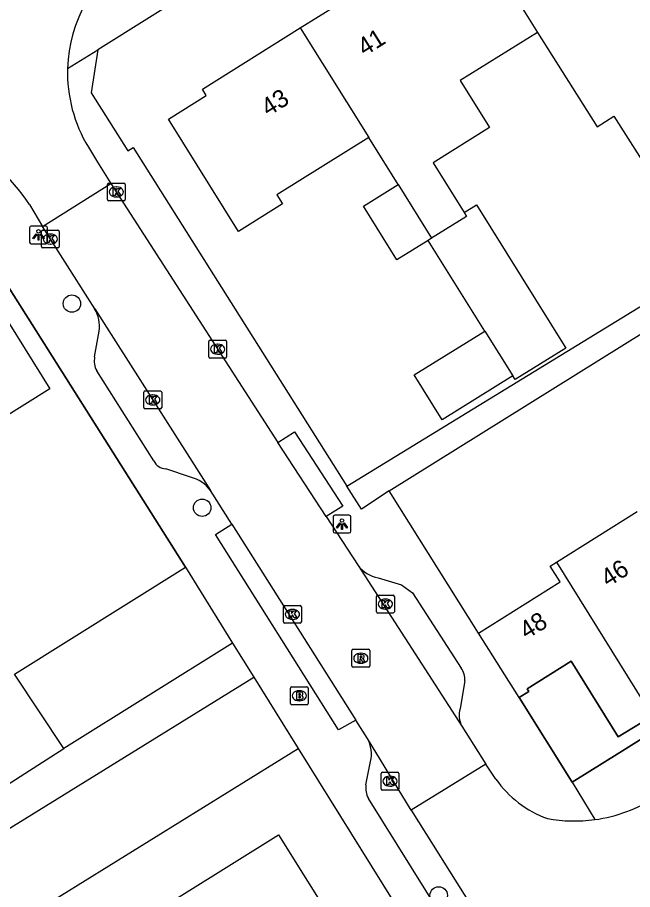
# Model space of a CAD drawing. Extents: x 159353 to 160616, y 385893 to 387321.
# Drawn here: x 159730.58 to 159765.06, y 386027.3 to 386076.22 of the extents above; entities that cross this region are included whole.
import ezdxf

# ---------------------------------------------------------------- set-up
doc = ezdxf.new("R2010")
doc.units = 0
for name, color, linetype in [('IMGEO_Boom', 7, 'Continuous'), ('IMGEO_Brandkraan', 7, 'Continuous'), ('IMGEO_Kolk', 7, 'Continuous'), ('IMGEO_Lichtpunt', 7, 'Continuous'), ('IMGEO_Muur', 7, 'Continuous'), ('IMGEO_Pand', 7, 'Continuous'), ('IMGEO_Pand_nummerreeks', 7, 'Continuous'), ('IMGEO_Pand_overbouw', 7, 'Continuous'), ('IMGEO_Rijbaan_lokaal_open', 7, 'Continuous'), ('IMGEO_Rioolput', 7, 'Continuous'), ('IMGEO_Voetpad_open', 7, 'Continuous')]:
    doc.layers.add(name, color=color, linetype=linetype)

msp = doc.modelspace()

# ---------------------------------------------------------------- linework, layer by layer
at = {"layer": 'IMGEO_Boom'}
for centre in [(159733.63, 386060.166), (159740.935, 386048.717), (159754.195, 386026.974)]:
    msp.add_circle(centre, 0.489, dxfattribs=at)
at = {"layer": 'IMGEO_Brandkraan'}
for p, q in [((159745.879, 386037.743), (159745.879, 386038.595)), ((159745.954, 386038.669), (159746.806, 386038.669)), ((159746.367, 386038.449), (159746.392, 386038.449)), ((159746.88, 386038.595), (159746.88, 386037.743)), ((159746.39, 386037.889), (159746.365, 386037.889)), ((159746.806, 386037.669), (159745.954, 386037.669))]:
    msp.add_line(p, q, dxfattribs=at)
for points in [[(159745.879, 386037.743), (159745.879, 386038.595)], [(159745.954, 386038.669), (159746.806, 386038.669)], [(159746.227, 386038.369), (159746.227, 386037.969), (159746.44, 386037.969)], [(159746.458, 386038.369), (159746.227, 386038.369)], [(159746.406, 386038.288), (159746.352, 386038.288), (159746.352, 386038.212)], [(159746.88, 386038.595), (159746.88, 386037.743)], [(159746.352, 386038.212), (159746.405, 386038.212)], [(159746.414, 386038.136), (159746.352, 386038.136), (159746.352, 386038.055)], [(159746.352, 386038.055), (159746.414, 386038.055)], [(159746.806, 386037.669), (159745.954, 386037.669)]]:
    msp.add_lwpolyline(points, dxfattribs=at)
for centre, radius, start, end in [((159745.956, 386038.593), 0.0765, 91.552, 178.448), ((159745.956, 386038.593), 0.0765, 91.552, 178.448), ((159746.407, 386038.25), 0.0379, 267.8285, 90.9355), ((159746.462, 386038.224), 0.145, 59.4692, 91.5367), ((159746.487, 386038.271), 0.0922, 285.5137, 58.1501), ((159746.804, 386038.593), 0.0765, 1.552, 88.448), ((159746.804, 386038.593), 0.0765, 1.552, 88.448), ((159745.956, 386037.745), 0.0765, 181.552, 268.448), ((159745.956, 386037.745), 0.0765, 181.552, 268.448), ((159746.415, 386038.095), 0.0404, 269.8759, 90.5077), ((159746.446, 386038.22), 0.251, 268.6676, 293.5347), ((159746.492, 386038.079), 0.105, 301.3115, 78.989), ((159746.804, 386037.745), 0.0765, 271.552, 358.448), ((159746.804, 386037.745), 0.0765, 271.552, 358.448)]:
    msp.add_arc(centre, radius, start, end, dxfattribs=at)
for centre, major_axis, ratio, start_param, end_param in [((159746.366, 386038.169), (-0.387, 0.002), 0.722429, 4.712389, 7.853982), ((159746.391, 386038.169), (-0.39, 0.002), 0.717154, 1.570796, 4.712389)]:
    msp.add_ellipse(centre, major_axis=major_axis, ratio=ratio, start_param=start_param, end_param=end_param, dxfattribs=at)
at = {"layer": 'IMGEO_Kolk'}
for p, q in [((159735.622, 386066.003), (159735.622, 386066.855)), ((159735.697, 386066.929), (159736.549, 386066.929)), ((159736.11, 386066.709), (159736.135, 386066.709)), ((159736.623, 386066.855), (159736.623, 386066.003)), ((159736.133, 386066.149), (159736.108, 386066.149)), ((159736.549, 386065.929), (159735.697, 386065.929)), ((159731.919, 386063.363), (159731.919, 386064.215)), ((159731.994, 386064.289), (159732.846, 386064.289)), ((159732.92, 386064.215), (159732.92, 386063.363)), ((159732.407, 386064.069), (159732.432, 386064.069)), ((159732.846, 386063.289), (159731.994, 386063.289)), ((159732.43, 386063.509), (159732.405, 386063.509)), ((159741.303, 386057.184), (159741.303, 386058.036)), ((159741.378, 386058.11), (159742.23, 386058.11)), ((159741.791, 386057.89), (159741.816, 386057.89)), ((159742.304, 386058.036), (159742.304, 386057.184)), ((159741.814, 386057.33), (159741.789, 386057.33)), ((159742.23, 386057.11), (159741.378, 386057.11)), ((159737.663, 386054.34), (159737.663, 386055.192)), ((159737.738, 386055.266), (159738.59, 386055.266)), ((159738.151, 386055.046), (159738.176, 386055.046)), ((159738.664, 386055.192), (159738.664, 386054.34)), ((159738.174, 386054.486), (159738.149, 386054.486)), ((159738.59, 386054.266), (159737.738, 386054.266)), ((159750.706, 386042.885), (159750.706, 386043.737)), ((159750.781, 386043.811), (159751.633, 386043.811)), ((159751.707, 386043.737), (159751.707, 386042.885)), ((159745.493, 386042.311), (159745.493, 386043.163)), ((159745.568, 386043.237), (159746.42, 386043.237)), ((159746.494, 386043.163), (159746.494, 386042.311)), ((159751.194, 386043.591), (159751.219, 386043.591)), ((159745.981, 386043.017), (159746.006, 386043.017)), ((159751.633, 386042.811), (159750.781, 386042.811)), ((159751.217, 386043.031), (159751.192, 386043.031)), ((159746.42, 386042.237), (159745.568, 386042.237)), ((159746.004, 386042.457), (159745.979, 386042.457)), ((159751.037, 386033.879), (159751.889, 386033.879)), ((159750.962, 386032.953), (159750.962, 386033.805)), ((159751.45, 386033.659), (159751.475, 386033.659)), ((159751.963, 386033.805), (159751.963, 386032.953)), ((159751.889, 386032.879), (159751.037, 386032.879)), ((159751.473, 386033.099), (159751.448, 386033.099))]:
    msp.add_line(p, q, dxfattribs=at)
for points in [[(159735.622, 386066.003), (159735.622, 386066.855)], [(159735.697, 386066.929), (159736.549, 386066.929)], [(159735.943, 386066.629), (159736.066, 386066.629), (159736.066, 386066.478), (159736.196, 386066.629), (159736.36, 386066.629), (159736.214, 386066.478), (159736.367, 386066.229), (159736.215, 386066.229), (159736.13, 386066.393), (159736.066, 386066.326), (159736.066, 386066.229), (159735.943, 386066.229), (159735.943, 386066.629)], [(159736.623, 386066.855), (159736.623, 386066.003)], [(159736.549, 386065.929), (159735.697, 386065.929)], [(159731.919, 386063.363), (159731.919, 386064.215)], [(159731.994, 386064.289), (159732.846, 386064.289)], [(159732.92, 386064.215), (159732.92, 386063.363)], [(159732.24, 386063.989), (159732.363, 386063.989), (159732.363, 386063.838), (159732.493, 386063.989), (159732.657, 386063.989), (159732.511, 386063.838), (159732.664, 386063.589), (159732.512, 386063.589), (159732.427, 386063.753), (159732.363, 386063.686), (159732.363, 386063.589), (159732.24, 386063.589), (159732.24, 386063.989)], [(159732.846, 386063.289), (159731.994, 386063.289)], [(159741.303, 386057.184), (159741.303, 386058.036)], [(159741.378, 386058.11), (159742.23, 386058.11)], [(159741.624, 386057.81), (159741.747, 386057.81), (159741.747, 386057.659), (159741.877, 386057.81), (159742.041, 386057.81), (159741.895, 386057.659), (159742.048, 386057.41), (159741.896, 386057.41), (159741.811, 386057.574), (159741.747, 386057.507), (159741.747, 386057.41), (159741.624, 386057.41), (159741.624, 386057.81)], [(159742.304, 386058.036), (159742.304, 386057.184)], [(159742.23, 386057.11), (159741.378, 386057.11)], [(159737.663, 386054.34), (159737.663, 386055.192)], [(159737.738, 386055.266), (159738.59, 386055.266)], [(159737.984, 386054.966), (159738.107, 386054.966), (159738.107, 386054.815), (159738.237, 386054.966), (159738.401, 386054.966), (159738.255, 386054.815), (159738.408, 386054.566), (159738.256, 386054.566), (159738.171, 386054.73), (159738.107, 386054.663), (159738.107, 386054.566), (159737.984, 386054.566), (159737.984, 386054.966)], [(159738.664, 386055.192), (159738.664, 386054.34)], [(159738.59, 386054.266), (159737.738, 386054.266)], [(159750.706, 386042.885), (159750.706, 386043.737)], [(159750.781, 386043.811), (159751.633, 386043.811)], [(159751.707, 386043.737), (159751.707, 386042.885)], [(159745.493, 386042.311), (159745.493, 386043.163)], [(159745.568, 386043.237), (159746.42, 386043.237)], [(159746.494, 386043.163), (159746.494, 386042.311)], [(159751.027, 386043.511), (159751.15, 386043.511), (159751.15, 386043.36), (159751.28, 386043.511), (159751.444, 386043.511), (159751.298, 386043.36), (159751.451, 386043.111), (159751.299, 386043.111), (159751.214, 386043.275), (159751.15, 386043.208), (159751.15, 386043.111), (159751.027, 386043.111), (159751.027, 386043.511)], [(159745.814, 386042.937), (159745.937, 386042.937), (159745.937, 386042.786), (159746.067, 386042.937), (159746.231, 386042.937), (159746.085, 386042.786), (159746.238, 386042.537), (159746.086, 386042.537), (159746.001, 386042.701), (159745.937, 386042.634), (159745.937, 386042.537), (159745.814, 386042.537), (159745.814, 386042.937)], [(159751.633, 386042.811), (159750.781, 386042.811)], [(159746.42, 386042.237), (159745.568, 386042.237)], [(159751.037, 386033.879), (159751.889, 386033.879)], [(159750.962, 386032.953), (159750.962, 386033.805)], [(159751.283, 386033.579), (159751.406, 386033.579), (159751.406, 386033.428), (159751.536, 386033.579), (159751.7, 386033.579), (159751.554, 386033.428), (159751.707, 386033.179), (159751.555, 386033.179), (159751.47, 386033.343), (159751.406, 386033.276), (159751.406, 386033.179), (159751.283, 386033.179), (159751.283, 386033.579)], [(159751.963, 386033.805), (159751.963, 386032.953)], [(159751.889, 386032.879), (159751.037, 386032.879)]]:
    msp.add_lwpolyline(points, dxfattribs=at)
for centre, start, end in [((159735.699, 386066.853), 91.552, 178.448), ((159735.699, 386066.853), 91.552, 178.448), ((159736.547, 386066.853), 1.552, 88.448), ((159736.547, 386066.853), 1.552, 88.448), ((159735.699, 386066.005), 181.552, 268.448), ((159735.699, 386066.005), 181.552, 268.448), ((159736.547, 386066.005), 271.552, 358.448), ((159736.547, 386066.005), 271.552, 358.448), ((159731.996, 386064.213), 91.552, 178.448), ((159731.996, 386064.213), 91.552, 178.448), ((159732.844, 386064.213), 1.552, 88.448), ((159732.844, 386064.213), 1.552, 88.448), ((159731.996, 386063.365), 181.552, 268.448), ((159731.996, 386063.365), 181.552, 268.448), ((159732.844, 386063.365), 271.552, 358.448), ((159732.844, 386063.365), 271.552, 358.448), ((159741.38, 386058.034), 91.552, 178.448), ((159741.38, 386058.034), 91.552, 178.448), ((159742.228, 386058.034), 1.552, 88.448), ((159742.228, 386058.034), 1.552, 88.448), ((159741.38, 386057.186), 181.552, 268.448), ((159741.38, 386057.186), 181.552, 268.448), ((159742.228, 386057.186), 271.552, 358.448), ((159742.228, 386057.186), 271.552, 358.448), ((159737.74, 386055.19), 91.552, 178.448), ((159737.74, 386055.19), 91.552, 178.448), ((159738.588, 386055.19), 1.552, 88.448), ((159738.588, 386055.19), 1.552, 88.448), ((159737.74, 386054.342), 181.552, 268.448), ((159737.74, 386054.342), 181.552, 268.448), ((159738.588, 386054.342), 271.552, 358.448), ((159738.588, 386054.342), 271.552, 358.448), ((159750.783, 386043.735), 91.552, 178.448), ((159750.783, 386043.735), 91.552, 178.448), ((159751.631, 386043.735), 1.552, 88.448), ((159751.631, 386043.735), 1.552, 88.448), ((159745.57, 386043.161), 91.552, 178.448), ((159745.57, 386043.161), 91.552, 178.448), ((159746.418, 386043.161), 1.552, 88.448), ((159746.418, 386043.161), 1.552, 88.448), ((159750.783, 386042.887), 181.552, 268.448), ((159750.783, 386042.887), 181.552, 268.448), ((159751.631, 386042.887), 271.552, 358.448), ((159751.631, 386042.887), 271.552, 358.448), ((159745.57, 386042.313), 181.552, 268.448), ((159745.57, 386042.313), 181.552, 268.448), ((159746.418, 386042.313), 271.552, 358.448), ((159746.418, 386042.313), 271.552, 358.448), ((159751.039, 386033.803), 91.552, 178.448), ((159751.039, 386033.803), 91.552, 178.448), ((159751.887, 386033.803), 1.552, 88.448), ((159751.887, 386033.803), 1.552, 88.448), ((159751.039, 386032.955), 181.552, 268.448), ((159751.039, 386032.955), 181.552, 268.448), ((159751.887, 386032.955), 271.552, 358.448), ((159751.887, 386032.955), 271.552, 358.448)]:
    msp.add_arc(centre, 0.0765, start, end, dxfattribs=at)
for centre, major_axis, ratio, start_param, end_param in [((159736.109, 386066.429), (-0.387, 0.002), 0.722429, 4.712389, 7.853982), ((159736.134, 386066.429), (-0.39, 0.002), 0.717154, 1.570796, 4.712389), ((159732.406, 386063.789), (-0.387, 0.002), 0.722429, 4.712389, 7.853982), ((159732.431, 386063.789), (-0.39, 0.002), 0.717154, 1.570796, 4.712389), ((159741.79, 386057.61), (-0.387, 0.002), 0.722429, 4.712389, 7.853982), ((159741.815, 386057.61), (-0.39, 0.002), 0.717154, 1.570796, 4.712389), ((159738.15, 386054.766), (-0.387, 0.002), 0.722429, 4.712389, 7.853982), ((159738.175, 386054.766), (-0.39, 0.002), 0.717154, 1.570796, 4.712389), ((159751.193, 386043.311), (-0.387, 0.002), 0.722429, 4.712389, 7.853982), ((159751.218, 386043.311), (-0.39, 0.002), 0.717154, 1.570796, 4.712389), ((159745.98, 386042.737), (-0.387, 0.002), 0.722429, 4.712389, 7.853982), ((159746.005, 386042.737), (-0.39, 0.002), 0.717154, 1.570796, 4.712389), ((159751.449, 386033.379), (-0.387, 0.002), 0.722429, 4.712389, 7.853982), ((159751.474, 386033.379), (-0.39, 0.002), 0.717154, 1.570796, 4.712389)]:
    msp.add_ellipse(centre, major_axis=major_axis, ratio=ratio, start_param=start_param, end_param=end_param, dxfattribs=at)
at = {"layer": 'IMGEO_Lichtpunt'}
for p, q in [((159731.262, 386064.423), (159731.262, 386063.616)), ((159731.262, 386064.423), (159731.262, 386063.616)), ((159732.164, 386064.518), (159731.356, 386064.518)), ((159732.164, 386064.518), (159731.356, 386064.518)), ((159732.258, 386063.616), (159732.258, 386064.423)), ((159732.258, 386063.616), (159732.258, 386064.423)), ((159731.356, 386063.522), (159732.164, 386063.522)), ((159731.356, 386063.522), (159732.164, 386063.522)), ((159748.273, 386048.204), (159748.273, 386047.397)), ((159748.273, 386048.204), (159748.273, 386047.397)), ((159749.175, 386048.299), (159748.367, 386048.299)), ((159749.175, 386048.299), (159748.367, 386048.299)), ((159749.269, 386047.397), (159749.269, 386048.204)), ((159749.269, 386047.397), (159749.269, 386048.204)), ((159748.367, 386047.303), (159749.175, 386047.303)), ((159748.367, 386047.303), (159749.175, 386047.303))]:
    msp.add_line(p, q, dxfattribs=at)
for points in [[(159731.636, 386064.087), (159731.675, 386064.059), (159731.487, 386063.797), (159731.449, 386063.824), (159731.636, 386064.087)], [(159731.738, 386064.039), (159731.785, 386064.039), (159731.785, 386063.717), (159731.738, 386063.717), (159731.738, 386064.039)], [(159731.848, 386064.059), (159731.886, 386064.086), (159732.073, 386063.824), (159732.034, 386063.796), (159731.848, 386064.059)], [(159748.647, 386047.868), (159748.686, 386047.84), (159748.498, 386047.578), (159748.46, 386047.605), (159748.647, 386047.868)], [(159748.749, 386047.82), (159748.796, 386047.82), (159748.796, 386047.498), (159748.749, 386047.498), (159748.749, 386047.82)], [(159748.859, 386047.84), (159748.897, 386047.867), (159749.084, 386047.605), (159749.045, 386047.577), (159748.859, 386047.84)]]:
    msp.add_lwpolyline(points, dxfattribs=at)
for centre in [(159731.761, 386064.221), (159748.772, 386048.002)]:
    msp.add_circle(centre, 0.0994, dxfattribs=at)
for centre, start, end in [((159731.356, 386064.423), 90, 180), ((159731.356, 386064.423), 90, 180), ((159732.164, 386064.423), 0, 90), ((159732.164, 386064.423), 0, 90), ((159731.356, 386063.616), 180, 270), ((159731.356, 386063.616), 180, 270), ((159732.164, 386063.616), 270, 0), ((159732.164, 386063.616), 270, 360), ((159748.367, 386048.204), 90, 180), ((159748.367, 386048.204), 90, 180), ((159749.175, 386048.204), 0, 90), ((159749.175, 386048.204), 0, 90), ((159748.367, 386047.397), 180, 270), ((159748.367, 386047.397), 180, 270), ((159749.175, 386047.397), 270, 0), ((159749.175, 386047.397), 270, 360)]:
    msp.add_arc(centre, 0.0946, start, end, dxfattribs=at)
at = {"layer": 'IMGEO_Muur'}
for points in [[(159739.998, 386045.377), (159726.053, 386067.427)], [(159756.434, 386041.685), (159751.412, 386049.66)]]:
    msp.add_lwpolyline(points, dxfattribs=at)
at = {"layer": 'IMGEO_Pand'}
for points in [[(159746.435, 386075.635), (159751.559, 386078.84), (159752.882, 386076.718), (159757.19, 386079.405)], [(159757.19, 386079.405), (159758.698, 386077.014), (159759.732, 386075.374)], [(159759.732, 386075.374), (159763.073, 386070.078), (159764.019, 386070.675), (159765.576, 386068.207), (159774.279, 386073.697), (159772.722, 386076.165), (159772.322, 386076.799)], [(159750.274, 386069.478), (159745.119, 386066.265), (159745.436, 386065.756), (159742.966, 386064.216), (159739.04, 386070.512), (159741.167, 386071.842), (159740.943, 386072.2), (159746.435, 386075.635)], [(159746.435, 386075.635), (159750.274, 386069.478)], [(159759.732, 386075.374), (159755.402, 386072.674), (159757.046, 386070.036), (159753.88, 386068.063), (159755.614, 386065.282)], [(159751.919, 386066.841), (159750.274, 386069.478)], [(159753.599, 386063.715), (159751.849, 386062.625), (159749.976, 386065.63), (159751.919, 386066.841)], [(159751.919, 386066.841), (159753.793, 386063.836)], [(159755.614, 386065.282), (159756.304, 386065.712), (159761.317, 386057.675), (159758.472, 386055.901), (159758.341, 386056.112)], [(159755.614, 386065.282), (159755.753, 386065.058), (159753.793, 386063.836)], [(159753.793, 386063.836), (159753.599, 386063.715)], [(159756.774, 386058.623), (159753.599, 386063.715)], [(159718.85, 386058.374), (159724.039, 386061.618), (159725.451, 386059.359), (159728.653, 386061.361), (159732.387, 386055.393), (159729.564, 386053.627), (159728.326, 386055.605), (159722.758, 386052.122)], [(159758.341, 386056.112), (159754.393, 386053.65), (159752.827, 386056.162), (159756.774, 386058.623)], [(159756.774, 386058.623), (159758.341, 386056.112)], [(159760.791, 386045.66), (159765.322, 386048.505)], [(159756.434, 386041.685), (159761.007, 386044.556), (159760.449, 386045.445), (159760.791, 386045.66)], [(159760.791, 386045.66), (159766.564, 386036.364)], [(159733.186, 386035.211), (159730.405, 386039.383), (159739.998, 386045.377)], [(159739.998, 386045.377), (159742.641, 386041.129)], [(159758.7, 386038.075), (159756.434, 386041.685)], [(159742.641, 386041.129), (159733.186, 386035.211)], [(159758.7, 386038.075), (159759.248, 386038.413), (159759.159, 386038.558), (159761.62, 386040.107), (159764.257, 386035.863), (159765.538, 386036.658), (159765.962, 386035.991)], [(159740.019, 386019.428), (159739.9, 386019.62), (159740.475, 386019.981), (159737.155, 386025.338), (159745.219, 386030.364), (159748.551, 386025.02), (159749.137, 386025.384), (159749.263, 386025.183)]]:
    msp.add_lwpolyline(points, dxfattribs=at)
at = {"layer": 'IMGEO_Pand_overbouw'}
msp.add_lwpolyline([(159758.7, 386038.075), (159761.674, 386033.329), (159764.352, 386034.991), (159765.962, 386035.991), (159765.538, 386036.658), (159764.257, 386035.863), (159761.62, 386040.107), (159759.159, 386038.558), (159759.248, 386038.413)], close=True, dxfattribs=at)
at = {"layer": 'IMGEO_Rijbaan_lokaal_open'}
for points in [[(159734.553, 386068.939), (159735.069, 386068.094), (159735.815, 386066.908)], [(159731.979, 386064.484), (159735.815, 386066.908)], [(159735.815, 386066.908), (159745.179, 386052.371)], [(159731.248, 386065.731), (159731.979, 386064.484)], [(159734.907, 386059.872), (159731.979, 386064.484)], [(159734.907, 386059.872), (159741.407, 386049.679)], [(159747.883, 386048.224), (159745.179, 386052.371)], [(159742.601, 386047.804), (159741.407, 386049.679)], [(159747.883, 386048.224), (159749.673, 386045.484)], [(159742.601, 386047.804), (159749.546, 386036.81)], [(159749.673, 386045.484), (159755.487, 386036.469)], [(159711.277, 386019.075), (159743.822, 386039.222)], [(159743.822, 386039.222), (159746.307, 386035.207)], [(159750.194, 386035.775), (159749.546, 386036.81)], [(159755.487, 386036.469), (159756.838, 386034.337)], [(159752.658, 386031.759), (159750.194, 386035.775)], [(159728.436, 386024.138), (159729.047, 386024.522), (159746.307, 386035.207)], [(159756.838, 386034.337), (159752.658, 386031.759)], [(159757.402, 386033.5), (159756.838, 386034.337)], [(159752.658, 386031.759), (159762.791, 386015.603)]]:
    msp.add_lwpolyline(points, dxfattribs=at)
for centre, radius, start, end in [((159741.429, 386073.115), 8.044, 122.3186, 178.2895), ((159741.442, 386073.118), 8.057, 178.3151, 211.2423), ((159721.478, 386059.203), 11.751, 33.7497, 60.6789), ((159762.267, 386036.85), 5.907, 214.5533, 250.4477), ((159761.802, 386039.568), 8.423, 277.8085, 303.0153), ((159761.809, 386039.56), 8.414, 259.6008, 277.7679)]:
    msp.add_arc(centre, radius, start, end, dxfattribs=at)
at = {"layer": 'IMGEO_Rioolput'}
for p, q in [((159749.327, 386039.851), (159749.327, 386040.703)), ((159749.402, 386040.777), (159750.254, 386040.777)), ((159750.328, 386040.703), (159750.328, 386039.851)), ((159749.815, 386040.557), (159749.84, 386040.557)), ((159750.254, 386039.777), (159749.402, 386039.777)), ((159749.838, 386039.997), (159749.813, 386039.997))]:
    msp.add_line(p, q, dxfattribs=at)
for points in [[(159749.327, 386039.851), (159749.327, 386040.703)], [(159749.402, 386040.777), (159750.254, 386040.777)], [(159750.328, 386040.703), (159750.328, 386039.851)], [(159749.916, 386040.475), (159749.664, 386040.477), (159749.664, 386040.077)], [(159749.664, 386040.077), (159749.788, 386040.077), (159749.788, 386040.239), (159749.799, 386040.239)], [(159749.842, 386040.396), (159749.788, 386040.396), (159749.788, 386040.315)], [(159749.788, 386040.315), (159749.84, 386040.315)], [(159749.846, 386040.21), (159749.917, 386040.077), (159750.057, 386040.077), (159749.992, 386040.203)], [(159750.254, 386039.777), (159749.402, 386039.777)]]:
    msp.add_lwpolyline(points, dxfattribs=at)
for centre, radius, start, end in [((159749.404, 386040.701), 0.0765, 91.552, 178.448), ((159749.404, 386040.701), 0.0765, 91.552, 178.448), ((159750.252, 386040.701), 0.0765, 1.552, 88.448), ((159750.252, 386040.701), 0.0765, 1.552, 88.448), ((159749.798, 386040.186), 0.0533, 26.0293, 88.6989), ((159749.824, 386040.504), 0.19, 274.7715, 282.9687), ((159749.848, 386040.3), 0.0964, 77.0061, 93.1865), ((159749.862, 386040.357), 0.0378, 276.6634, 79.6772), ((159749.915, 386040.365), 0.109, 350.3612, 89.416), ((159749.913, 386040.365), 0.112, 277.5842, 350.9817), ((159749.897, 386040.15), 0.108, 29.5134, 73.7905), ((159749.404, 386039.853), 0.0765, 181.552, 268.448), ((159749.404, 386039.853), 0.0765, 181.552, 268.448), ((159750.252, 386039.853), 0.0765, 271.552, 358.448), ((159750.252, 386039.853), 0.0765, 271.552, 358.448)]:
    msp.add_arc(centre, radius, start, end, dxfattribs=at)
for centre, major_axis, ratio, start_param, end_param in [((159749.814, 386040.277), (-0.387, 0.002), 0.722429, 4.712389, 7.853982), ((159749.839, 386040.277), (-0.39, 0.002), 0.717154, 1.570796, 4.712389)]:
    msp.add_ellipse(centre, major_axis=major_axis, ratio=ratio, start_param=start_param, end_param=end_param, dxfattribs=at)
at = {"layer": 'IMGEO_Voetpad_open'}
for points in [[(159846.595, 386144.231), (159735.083, 386074.392)], [(159751.412, 386049.66), (159862.072, 386118.665)], [(159749.045, 386049.918), (159785.705, 386072.384), (159811.147, 386088.283)], [(159733.388, 386073.355), (159735.083, 386074.392)], [(159735.083, 386074.392), (159734.716, 386071.987), (159736.771, 386068.736), (159737.062, 386068.923), (159749.045, 386049.918)], [(159724.652, 386067.823), (159726.053, 386067.427), (159739.998, 386045.377)], [(159734.906, 386057.179), (159735.16, 386058.627)], [(159738.227, 386051.347), (159735.021, 386056.397)], [(159745.179, 386052.371), (159746.105, 386052.968), (159748.811, 386048.809), (159747.883, 386048.224)], [(159740.28, 386050.429), (159738.891, 386050.907)], [(159751.412, 386049.66), (159749.859, 386048.628), (159749.045, 386049.918)], [(159756.434, 386041.685), (159751.412, 386049.66)], [(159749.546, 386036.81), (159748.568, 386036.254), (159741.681, 386047.216), (159742.601, 386047.804)], [(159750.795, 386044.778), (159752.115, 386044.4), (159752.734, 386043.944), (159755.456, 386039.725)], [(159742.641, 386041.129), (159743.822, 386039.222)], [(159755.666, 386039.015), (159755.391, 386037.448)], [(159761.674, 386033.329), (159758.7, 386038.075)], [(159765.962, 386035.991), (159764.352, 386034.991), (159761.674, 386033.329)], [(159712.435, 386021.927), (159733.186, 386035.211)], [(159746.307, 386035.207), (159771.719, 385994.399)], [(159750.109, 386033.166), (159750.371, 386034.478)], [(159761.674, 386033.329), (159762.946, 386031.223)], [(159773.04, 385995.833), (159750.25, 386032.416)]]:
    msp.add_lwpolyline(points, dxfattribs=at)
for centre, radius, start, end in [((159733.215, 386058.88), 1.961, 352.5906, 30.383), ((159736.045, 386056.947), 1.163, 168.4951, 208.2367), ((159738.912, 386051.659), 0.753, 204.5261, 268.413), ((159739.786, 386048.465), 2.025, 36.8274, 75.8863), ((159751.155, 386046.595), 1.852, 216.8548, 258.7862), ((159754.441, 386039.039), 1.225, 358.8862, 34.0675), ((159756.711, 386037.083), 1.369, 164.5472, 206.6538), ((159748.641, 386034.902), 1.781, 346.2146, 29.3275), ((159751.443, 386033.029), 1.342, 174.1225, 207.1721)]:
    msp.add_arc(centre, radius, start, end, dxfattribs=at)

# ---------------------------------------------------------------- texts
at = {"layer": 'IMGEO_Pand_nummerreeks'}
for s, rotation, p in [('41', 32.0226, (159750.04, 386074.021)), ('43', 32.0248, (159744.636, 386070.641)), ('46', 32.5898, (159763.693, 386044.238)), ('48', 31.7169, (159759.115, 386041.305))]:
    msp.add_text(s, height=1, rotation=rotation, dxfattribs=at).set_placement(p)

doc.saveas('drawing.dxf')
